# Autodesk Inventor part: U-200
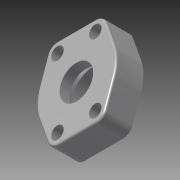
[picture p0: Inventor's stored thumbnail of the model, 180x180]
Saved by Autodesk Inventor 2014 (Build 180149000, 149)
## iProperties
Created: 2011-01
Part Number: U-200
Material: Steel
Document SubType Name: Modeling
Designer: deckm
Density: 7.85 g/cm^3
Description: FLARED FLANGE SAE WITH CLEARANCE HOLES
Mass: 259.498 g
Surface Area: 100.719 cm^2
Volume: 33.0571 cm^3
Appearance: Steel
Author: deckm
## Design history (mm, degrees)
derived "union_cap.ipt"
body "Solid1"
feature "Solid1::union_cap.ipt"
tag "TaggingFeature1"
other parameters: "d1" = 102.108, "d3" = 19.10263, "d25" = 42.926, "FilletTop" = 2, "d27" = 25.4, "d28" = 37 deg, "d29" = 30.988, "d30" = 19.05, "FilletCorners" = 12.192, "FilletEnds" = 48.387, "d8" = 30.988, "d9" = 0, "d12" = 14.2875, "d21" = 42.926, "d24" = 77.724
